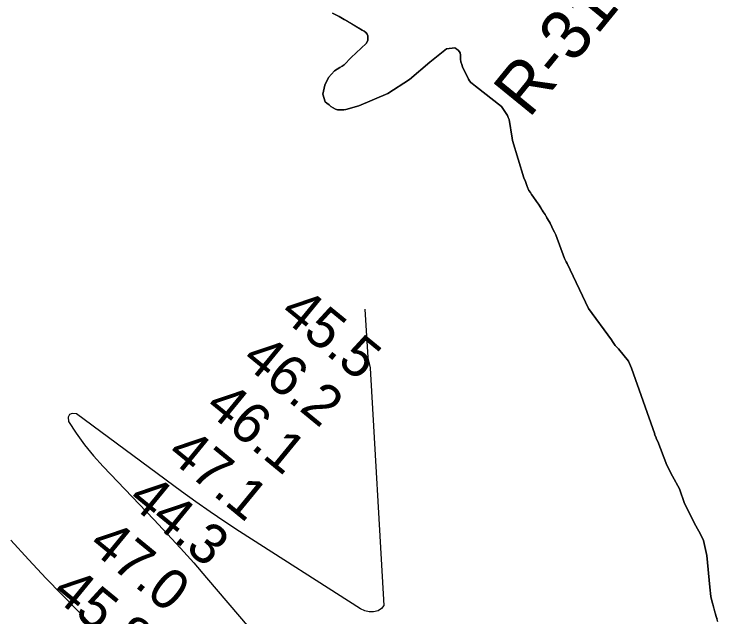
# Model space of a CAD drawing. Extents: x 3172231 to 3210228, y 940198 to 965780.
# Drawn here: x 3194853 to 3196024, y 947239 to 948241 of the extents above; entities that cross this region are included whole.
import ezdxf

# ---------------------------------------------------------------- set-up
doc = ezdxf.new("R2010")
doc.units = 0
for name, color, linetype in [('V-RIVR-RANG', 7, 'Continuous'), ('V-RIVR-RANG-IDEN', 7, 'Continuous'), ('V-SITE-VEGE', 7, 'Continuous'), ('V-TOPO-MINR', 7, 'Continuous'), ('V-TOPO-SHOR', 7, 'Continuous')]:
    doc.layers.add(name, color=color, linetype=linetype)

msp = doc.modelspace()

# ---------------------------------------------------------------- linework, layer by layer
at = {"layer": 'V-SITE-VEGE'}
for p, q in [((3195393.656, 948237.225), (3195382.517, 948242.53)), ((3195402.155, 948232.327), (3195393.656, 948237.225)), ((3195431.888, 948214.398), (3195402.155, 948232.327)), ((3195435.374, 948212.75), (3195431.888, 948214.398)), ((3195438.067, 948210.728), (3195435.374, 948212.75)), ((3195440.35, 948207.935), (3195438.067, 948210.728)), ((3195441.452, 948204.775), (3195440.35, 948207.935)), ((3195441.268, 948196.947), (3195441.452, 948204.775)), ((3195413.593, 948169.011), (3195438.409, 948191.924)), ((3195438.409, 948191.924), (3195441.268, 948196.947)), ((3195572.344, 948183.357), (3195544.473, 948160.962)), ((3195585.877, 948184.934), (3195572.344, 948183.357)), ((3195592.039, 948180.481), (3195585.877, 948184.934)), ((3195595.085, 948176.885), (3195592.039, 948180.481)), ((3195401.946, 948156.753), (3195413.593, 948169.011)), ((3195595.384, 948172.963), (3195595.085, 948176.885)), ((3195595.619, 948166.299), (3195595.384, 948172.963)), ((3195398.759, 948154.48), (3195401.946, 948156.753)), ((3195544.473, 948160.962), (3195510.615, 948132.253)), ((3195595.91, 948161.988), (3195595.619, 948166.299)), ((3195597.364, 948157.253), (3195595.91, 948161.988)), ((3195598.839, 948153.3), (3195597.364, 948157.253)), ((3195375.791, 948135.405), (3195386.041, 948146.554)), ((3195386.041, 948146.554), (3195394.79, 948152.223)), ((3195394.79, 948152.223), (3195398.759, 948154.48)), ((3195608.927, 948132.704), (3195598.839, 948153.3)), ((3195369.969, 948122.941), (3195375.791, 948135.405)), ((3195366.653, 948108.046), (3195369.969, 948122.941)), ((3195510.615, 948132.253), (3195474.439, 948108.842)), ((3195610.428, 948129.924), (3195608.927, 948132.704)), ((3195612.331, 948127.53), (3195610.428, 948129.924)), ((3195620.41, 948121.466), (3195612.331, 948127.53)), ((3195663.474, 948087.56), (3195620.41, 948121.466)), ((3195370.347, 948095.231), (3195366.653, 948108.046)), ((3195474.439, 948108.842), (3195426.186, 948088.438)), ((3195373.041, 948093.212), (3195370.347, 948095.231)), ((3195376.881, 948089.988), (3195373.041, 948093.212)), ((3195379.946, 948087.175), (3195376.881, 948089.988)), ((3195383.815, 948085.127), (3195379.946, 948087.175)), ((3195426.186, 948088.438), (3195404.903, 948082.673)), ((3195673.691, 948072.439), (3195663.474, 948087.56)), ((3195387.293, 948083.087), (3195383.815, 948085.127)), ((3195390.787, 948081.827), (3195387.293, 948083.087)), ((3195397.44, 948081.674), (3195390.787, 948081.827)), ((3195401.362, 948081.973), (3195397.44, 948081.674)), ((3195404.903, 948082.673), (3195401.362, 948081.973)), ((3195674.793, 948069.281), (3195673.691, 948072.439)), ((3195676.276, 948065.722), (3195674.793, 948069.281)), ((3195681.418, 948034.666), (3195676.276, 948065.722)), ((3195681.717, 948030.742), (3195681.418, 948034.666)), ((3195701.018, 947968.806), (3195681.717, 948030.742)), ((3195703.619, 947962.871), (3195701.018, 947968.806)), ((3195704.71, 947959.322), (3195703.619, 947962.871)), ((3195705.812, 947956.166), (3195704.71, 947959.322)), ((3195709.14, 947947.861), (3195705.812, 947956.166)), ((3195711.796, 947944.275), (3195709.14, 947947.861)), ((3195713.68, 947941.099), (3195711.796, 947944.275)), ((3195715.964, 947938.303), (3195713.68, 947941.099)), ((3195721.633, 947929.554), (3195715.964, 947938.303)), ((3195725.055, 947925.165), (3195721.633, 947929.554)), ((3195729.221, 947919.196), (3195725.055, 947925.165)), ((3195732.979, 947912.449), (3195729.221, 947919.196)), ((3195735.999, 947907.68), (3195732.979, 947912.449)), ((3195739.002, 947902.125), (3195735.999, 947907.68)), ((3195742.778, 947896.164), (3195739.002, 947902.125)), ((3195744.28, 947893.387), (3195742.778, 947896.164)), ((3195747.272, 947887.443), (3195744.28, 947893.387)), ((3195749.137, 947883.482), (3195747.272, 947887.443)), ((3195751.767, 947878.723), (3195749.137, 947883.482)), ((3195754.003, 947873.97), (3195751.767, 947878.723)), ((3195768.348, 947834.474), (3195754.003, 947873.97)), ((3195770.967, 947829.321), (3195768.348, 947834.474)), ((3195772.851, 947826.145), (3195770.967, 947829.321)), ((3195808.39, 947751.638), (3195772.851, 947826.145)), ((3195846.628, 947699.49), (3195808.39, 947751.638)), ((3195848.129, 947696.713), (3195846.628, 947699.49)), ((3195850.395, 947693.135), (3195848.129, 947696.713)), ((3195852.668, 947689.951), (3195850.395, 947693.135)), ((3195855.728, 947686.745), (3195852.668, 947689.951)), ((3195858.03, 947684.732), (3195855.728, 947686.745)), ((3195874.772, 947663.976), (3195858.03, 947684.732)), ((3195879.984, 947652.499), (3195874.772, 947663.976)), ((3195918.515, 947542.337), (3195879.984, 947652.499)), ((3195918.114, 947541.954), (3195918.515, 947542.337)), ((3195920.379, 947538.376), (3195918.114, 947541.954)), ((3195921.452, 947534.045), (3195920.379, 947538.376)), ((3195923.717, 947530.467), (3195921.452, 947534.045)), ((3195938.844, 947490.951), (3195923.717, 947530.467)), ((3195947.832, 947472.748), (3195938.844, 947490.951)), ((3195959.459, 947451.699), (3195947.832, 947472.748)), ((3195967.89, 947427.221), (3195959.459, 947451.699)), ((3195986.605, 947390.363), (3195967.89, 947427.221)), ((3195994.502, 947376.471), (3195986.605, 947390.363)), ((3195999.733, 947365.775), (3195994.502, 947376.471)), ((3196005.025, 947340.98), (3195999.733, 947365.775)), ((3196010.296, 947288.145), (3196005.025, 947340.98)), ((3196011.642, 947272.687), (3196010.296, 947288.145)), ((3196014.163, 947263.229), (3196011.642, 947272.687)), ((3196015.25, 947259.678), (3196014.163, 947263.229)), ((3196020.645, 947239.19), (3196015.25, 947259.678)), ((3196023.573, 947230.504), (3196020.645, 947239.19))]:
    msp.add_line(p, q, dxfattribs=at)
at = {"layer": 'V-TOPO-MINR'}
for points in [[(3195436.368, 947750.699), (3195441.238, 947670.263), (3195441.616, 947666.965), (3195442.8, 947662.121), (3195443.249, 947660.515), (3195444.135, 947657.3), (3195444.37, 947656.44), (3195445.189, 947652.326), (3195467.685, 947257.502), (3195464.035, 947252.808), (3195458.594, 947248.896), (3195450.964, 947247.246), (3195443.482, 947246.988), (3195436.222, 947248.815), (3195429.11, 947252.034), (3195228.021, 947380.722), (3195203.453, 947396.79), (3195179.107, 947413.179), (3195155.091, 947430.049), (3195131.295, 947447.239), (3194956.584, 947576.117), (3194949.687, 947576.903), (3194944.818, 947575.482), (3194942.993, 947570.751), (3194943.196, 947563.812), (3194956.281, 947543.982), (3194970.166, 947524.77), (3194985.248, 947506.484), (3195001.129, 947488.814), (3195085.348, 947400.938), (3195107.792, 947377.103), (3195129.953, 947353.011), (3195151.687, 947328.533), (3195173.137, 947303.799), (3195334.26, 947114.671)], [(3194983.737, 947223.534), (3194906.519, 947302.815), (3194876.735, 947334.333), (3194847.605, 947366.426)]]:
    msp.add_lwpolyline(points, dxfattribs=at)
at = {"layer": 'V-TOPO-SHOR'}
for points in [[(3195382.517, 948242.53), (3195393.656, 948237.225), (3195396.357, 948235.595), (3195402.155, 948232.327), (3195405.632, 948230.289), (3195431.888, 948214.398), (3195435.374, 948212.75), (3195438.067, 948210.728), (3195440.35, 948207.935), (3195441.452, 948204.775), (3195441.368, 948201.252), (3195441.268, 948196.947), (3195438.409, 948191.924), (3195413.591, 948169.011), (3195401.946, 948156.753), (3195398.759, 948154.48), (3195394.79, 948152.223), (3195386.041, 948146.554), (3195375.791, 948135.405), (3195369.969, 948122.941), (3195366.653, 948108.046), (3195370.347, 948095.231), (3195373.041, 948093.212), (3195376.881, 948089.988), (3195379.946, 948087.175), (3195383.815, 948085.127), (3195387.293, 948083.087), (3195390.787, 948081.829), (3195397.44, 948081.674), (3195401.362, 948081.973), (3195404.903, 948082.673), (3195426.186, 948088.438), (3195474.439, 948108.842), (3195510.615, 948132.253), (3195544.473, 948160.962), (3195572.344, 948183.357), (3195585.877, 948184.934), (3195589.342, 948182.503), (3195592.037, 948180.481), (3195595.085, 948176.885), (3195595.384, 948172.963), (3195595.619, 948166.299), (3195595.91, 948161.986), (3195597.364, 948157.253), (3195598.839, 948153.3), (3195608.927, 948132.702), (3195610.428, 948129.924), (3195612.331, 948127.53), (3195615.024, 948125.509), (3195617.717, 948123.488), (3195620.41, 948121.466), (3195663.474, 948087.56), (3195673.691, 948072.439), (3195674.793, 948069.281), (3195676.276, 948065.722), (3195681.418, 948034.666), (3195681.717, 948030.742), (3195701.018, 947968.806), (3195703.619, 947962.871), (3195704.71, 947959.322), (3195705.812, 947956.164), (3195707.657, 947951.421), (3195709.14, 947947.861), (3195711.796, 947944.275), (3195713.68, 947941.099), (3195715.964, 947938.303), (3195721.633, 947929.554), (3195725.055, 947925.165), (3195729.221, 947919.196), (3195731.477, 947915.226), (3195732.979, 947912.449), (3195735.999, 947907.68), (3195737.501, 947904.903), (3195739.002, 947902.125), (3195742.778, 947896.164), (3195744.28, 947893.387), (3195747.272, 947887.443), (3195749.137, 947883.482), (3195751.767, 947878.723), (3195754.003, 947873.97), (3195768.348, 947834.474), (3195770.967, 947829.321), (3195772.851, 947826.145), (3195808.39, 947751.638), (3195846.628, 947699.49), (3195848.129, 947696.713), (3195850.395, 947693.135)], [(3195850.395, 947693.135), (3195852.67, 947689.951), (3195855.728, 947686.745), (3195858.03, 947684.732), (3195874.772, 947663.976), (3195879.984, 947652.499), (3195918.513, 947542.337), (3195918.114, 947541.954), (3195920.379, 947538.376), (3195921.452, 947534.045), (3195923.717, 947530.467), (3195938.844, 947490.951), (3195947.832, 947472.748), (3195959.459, 947451.699), (3195967.89, 947427.221), (3195986.605, 947390.363), (3195994.502, 947376.471), (3195999.733, 947365.775), (3196005.025, 947340.98), (3196010.296, 947288.145), (3196011.644, 947272.687), (3196014.163, 947263.229), (3196015.252, 947259.678), (3196018.126, 947248.645), (3196020.645, 947239.19), (3196022.109, 947234.846)]]:
    msp.add_lwpolyline(points, dxfattribs=at)

# ---------------------------------------------------------------- texts
at = {"layer": 'V-RIVR-RANG'}
for s, p in [('45.5', (3195292.232, 947739.721)), ('46.2', (3195229.032, 947662.224)), ('46.1', (3195167.668, 947583.222)), ('47.1', (3195104.468, 947505.725)), ('44.3', (3195039.433, 947429.733)), ('47.0', (3194973.989, 947354.076)), ('45.8', (3194913.033, 947274.739))]:
    msp.add_text(s, height=67, rotation=320.658326, dxfattribs=at).set_placement(p)
at = {"layer": 'V-RIVR-RANG-IDEN'}
msp.add_text('R-313.85', height=82.9998, rotation=50.802318, dxfattribs=at).set_placement((3195709.254, 948066.353))

doc.saveas('drawing.dxf')
